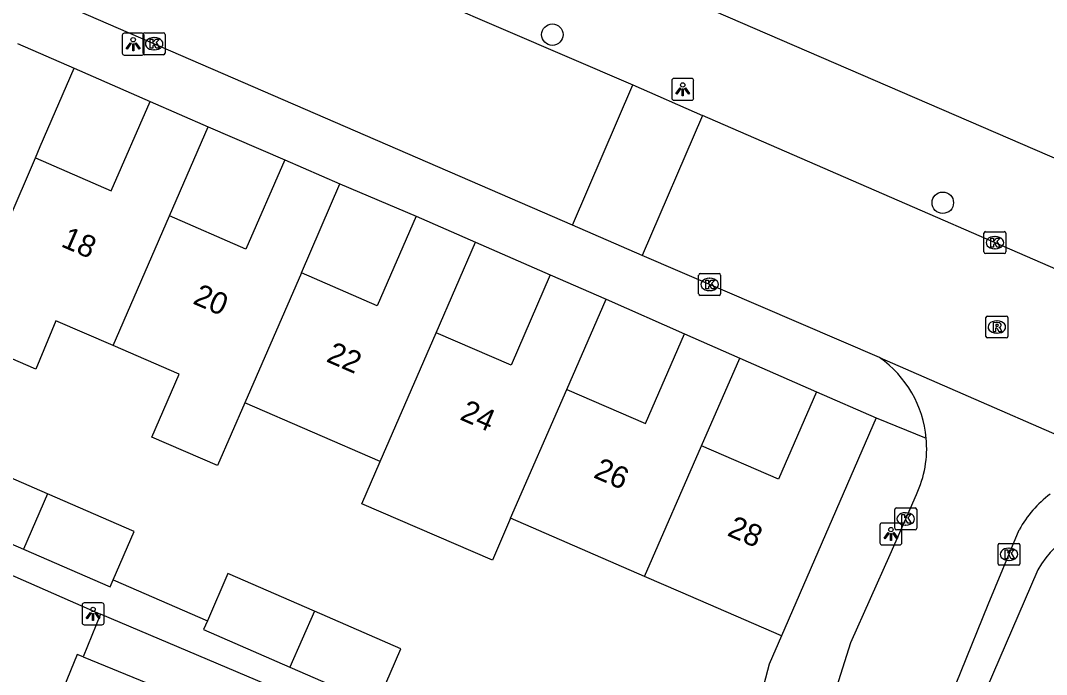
# Model space of a CAD drawing. Extents: x 162812 to 163818, y 381639 to 382470.
# Drawn here: x 163306.17 to 163352.9, y 381949.74 to 381979.54 of the extents above; entities that cross this region are included whole.
import ezdxf

# ---------------------------------------------------------------- set-up
doc = ezdxf.new("R2010")
doc.units = 0
for name, color, linetype in [('IMGEO_Boom', 7, 'Continuous'), ('IMGEO_Kolk', 7, 'Continuous'), ('IMGEO_Lichtpunt', 7, 'Continuous'), ('IMGEO_Pand', 7, 'Continuous'), ('IMGEO_Pand_nummerreeks', 7, 'Continuous'), ('IMGEO_Rijbaan_lokaal_open', 7, 'Continuous'), ('IMGEO_Rioolput', 7, 'Continuous'), ('IMGEO_Voetpad_open', 7, 'Continuous')]:
    doc.layers.add(name, color=color, linetype=linetype)

msp = doc.modelspace()

# ---------------------------------------------------------------- linework, layer by layer
at = {"layer": 'IMGEO_Boom'}
for centre in [(163330.392, 381978.896), (163348.173, 381971.236)]:
    msp.add_circle(centre, 0.489, dxfattribs=at)
at = {"layer": 'IMGEO_Kolk'}
for p, q in [((163311.756, 381978.057), (163311.756, 381978.909)), ((163311.831, 381978.983), (163312.683, 381978.983)), ((163312.244, 381978.763), (163312.269, 381978.763)), ((163312.757, 381978.909), (163312.757, 381978.057)), ((163312.683, 381977.983), (163311.831, 381977.983)), ((163312.267, 381978.203), (163312.242, 381978.203)), ((163350.121, 381969.919), (163350.973, 381969.919)), ((163350.046, 381968.993), (163350.046, 381969.845)), ((163350.534, 381969.699), (163350.559, 381969.699)), ((163351.047, 381969.845), (163351.047, 381968.993)), ((163350.557, 381969.139), (163350.532, 381969.139)), ((163350.973, 381968.919), (163350.121, 381968.919)), ((163337.13, 381968.015), (163337.982, 381968.015)), ((163337.055, 381967.089), (163337.055, 381967.941)), ((163337.543, 381967.795), (163337.568, 381967.795)), ((163338.056, 381967.941), (163338.056, 381967.089)), ((163337.566, 381967.235), (163337.541, 381967.235)), ((163337.982, 381967.015), (163337.13, 381967.015)), ((163345.986, 381956.405), (163345.986, 381957.257)), ((163346.061, 381957.331), (163346.913, 381957.331)), ((163346.987, 381957.257), (163346.987, 381956.405)), ((163346.474, 381957.111), (163346.499, 381957.111)), ((163346.913, 381956.331), (163346.061, 381956.331)), ((163346.497, 381956.551), (163346.472, 381956.551)), ((163350.688, 381954.792), (163350.688, 381955.644)), ((163350.763, 381955.718), (163351.615, 381955.718)), ((163351.176, 381955.498), (163351.201, 381955.498)), ((163351.689, 381955.644), (163351.689, 381954.792)), ((163351.199, 381954.938), (163351.174, 381954.938)), ((163351.615, 381954.718), (163350.763, 381954.718))]:
    msp.add_line(p, q, dxfattribs=at)
for points in [[(163311.756, 381978.057), (163311.756, 381978.909)], [(163311.831, 381978.983), (163312.683, 381978.983)], [(163312.757, 381978.909), (163312.757, 381978.057)], [(163312.077, 381978.683), (163312.2, 381978.683), (163312.2, 381978.532), (163312.33, 381978.683), (163312.494, 381978.683), (163312.348, 381978.532), (163312.501, 381978.283), (163312.349, 381978.283), (163312.264, 381978.447), (163312.2, 381978.38), (163312.2, 381978.283), (163312.077, 381978.283), (163312.077, 381978.683)], [(163312.683, 381977.983), (163311.831, 381977.983)], [(163350.121, 381969.919), (163350.973, 381969.919)], [(163350.046, 381968.993), (163350.046, 381969.845)], [(163350.367, 381969.619), (163350.49, 381969.619), (163350.49, 381969.468), (163350.62, 381969.619), (163350.784, 381969.619), (163350.638, 381969.468), (163350.791, 381969.219), (163350.639, 381969.219), (163350.554, 381969.383), (163350.49, 381969.316), (163350.49, 381969.219), (163350.367, 381969.219), (163350.367, 381969.619)], [(163351.047, 381969.845), (163351.047, 381968.993)], [(163350.973, 381968.919), (163350.121, 381968.919)], [(163337.13, 381968.015), (163337.982, 381968.015)], [(163337.055, 381967.089), (163337.055, 381967.941)], [(163337.376, 381967.715), (163337.499, 381967.715), (163337.499, 381967.564), (163337.629, 381967.715), (163337.793, 381967.715), (163337.647, 381967.564), (163337.8, 381967.315), (163337.648, 381967.315), (163337.563, 381967.479), (163337.499, 381967.412), (163337.499, 381967.315), (163337.376, 381967.315), (163337.376, 381967.715)], [(163338.056, 381967.941), (163338.056, 381967.089)], [(163337.982, 381967.015), (163337.13, 381967.015)], [(163345.986, 381956.405), (163345.986, 381957.257)], [(163346.061, 381957.331), (163346.913, 381957.331)], [(163346.987, 381957.257), (163346.987, 381956.405)], [(163346.307, 381957.031), (163346.43, 381957.031), (163346.43, 381956.88), (163346.56, 381957.031), (163346.724, 381957.031), (163346.578, 381956.88), (163346.731, 381956.631), (163346.579, 381956.631), (163346.494, 381956.795), (163346.43, 381956.728), (163346.43, 381956.631), (163346.307, 381956.631), (163346.307, 381957.031)], [(163346.913, 381956.331), (163346.061, 381956.331)], [(163350.688, 381954.792), (163350.688, 381955.644)], [(163350.763, 381955.718), (163351.615, 381955.718)], [(163351.009, 381955.418), (163351.132, 381955.418), (163351.132, 381955.267), (163351.262, 381955.418), (163351.426, 381955.418), (163351.28, 381955.267), (163351.433, 381955.018), (163351.281, 381955.018), (163351.196, 381955.182), (163351.132, 381955.115), (163351.132, 381955.018), (163351.009, 381955.018), (163351.009, 381955.418)], [(163351.689, 381955.644), (163351.689, 381954.792)], [(163351.615, 381954.718), (163350.763, 381954.718)]]:
    msp.add_lwpolyline(points, dxfattribs=at)
for centre, start, end in [((163311.833, 381978.907), 91.552, 178.448), ((163311.833, 381978.907), 91.552, 178.448), ((163312.681, 381978.907), 1.552, 88.448), ((163312.681, 381978.907), 1.552, 88.448), ((163311.833, 381978.059), 181.552, 268.448), ((163311.833, 381978.059), 181.552, 268.448), ((163312.681, 381978.059), 271.552, 358.448), ((163312.681, 381978.059), 271.552, 358.448), ((163350.123, 381969.843), 91.552, 178.448), ((163350.123, 381969.843), 91.552, 178.448), ((163350.971, 381969.843), 1.552, 88.448), ((163350.971, 381969.843), 1.552, 88.448), ((163350.123, 381968.995), 181.552, 268.448), ((163350.123, 381968.995), 181.552, 268.448), ((163350.971, 381968.995), 271.552, 358.448), ((163350.971, 381968.995), 271.552, 358.448), ((163337.132, 381967.939), 91.552, 178.448), ((163337.132, 381967.939), 91.552, 178.448), ((163337.98, 381967.939), 1.552, 88.448), ((163337.98, 381967.939), 1.552, 88.448), ((163337.132, 381967.091), 181.552, 268.448), ((163337.132, 381967.091), 181.552, 268.448), ((163337.98, 381967.091), 271.552, 358.448), ((163337.98, 381967.091), 271.552, 358.448), ((163346.063, 381957.255), 91.552, 178.448), ((163346.063, 381957.255), 91.552, 178.448), ((163346.911, 381957.255), 1.552, 88.448), ((163346.911, 381957.255), 1.552, 88.448), ((163346.063, 381956.407), 181.552, 268.448), ((163346.063, 381956.407), 181.552, 268.448), ((163346.911, 381956.407), 271.552, 358.448), ((163346.911, 381956.407), 271.552, 358.448), ((163350.765, 381955.642), 91.552, 178.448), ((163350.765, 381955.642), 91.552, 178.448), ((163351.613, 381955.642), 1.552, 88.448), ((163351.613, 381955.642), 1.552, 88.448), ((163350.765, 381954.794), 181.552, 268.448), ((163350.765, 381954.794), 181.552, 268.448), ((163351.613, 381954.794), 271.552, 358.448), ((163351.613, 381954.794), 271.552, 358.448)]:
    msp.add_arc(centre, 0.0765, start, end, dxfattribs=at)
for centre, major_axis, ratio, start_param, end_param in [((163312.243, 381978.483), (-0.387, 0.002), 0.722429, 4.712389, 7.853982), ((163312.268, 381978.483), (-0.39, 0.002), 0.717154, 1.570796, 4.712389), ((163350.533, 381969.419), (-0.387, 0.002), 0.722429, 4.712389, 7.853982), ((163350.558, 381969.419), (-0.39, 0.002), 0.717154, 1.570796, 4.712389), ((163337.542, 381967.515), (-0.387, 0.002), 0.722429, 4.712389, 7.853982), ((163337.567, 381967.515), (-0.39, 0.002), 0.717154, 1.570796, 4.712389), ((163346.473, 381956.831), (-0.387, 0.002), 0.722429, 4.712389, 7.853982), ((163346.498, 381956.831), (-0.39, 0.002), 0.717154, 1.570796, 4.712389), ((163351.175, 381955.218), (-0.387, 0.002), 0.722429, 4.712389, 7.853982), ((163351.2, 381955.218), (-0.39, 0.002), 0.717154, 1.570796, 4.712389)]:
    msp.add_ellipse(centre, major_axis=major_axis, ratio=ratio, start_param=start_param, end_param=end_param, dxfattribs=at)
at = {"layer": 'IMGEO_Lichtpunt'}
for p, q in [((163310.802, 381978.865), (163310.802, 381978.058)), ((163310.802, 381978.865), (163310.802, 381978.058)), ((163311.704, 381978.96), (163310.896, 381978.96)), ((163311.704, 381978.96), (163310.896, 381978.96)), ((163311.798, 381978.058), (163311.798, 381978.865)), ((163311.798, 381978.058), (163311.798, 381978.865)), ((163310.896, 381977.964), (163311.704, 381977.964)), ((163310.896, 381977.964), (163311.704, 381977.964)), ((163336.733, 381976.903), (163335.925, 381976.903)), ((163336.733, 381976.903), (163335.925, 381976.903)), ((163335.831, 381976.808), (163335.831, 381976.001)), ((163335.831, 381976.808), (163335.831, 381976.001)), ((163336.827, 381976.001), (163336.827, 381976.808)), ((163336.827, 381976.001), (163336.827, 381976.808)), ((163335.925, 381975.907), (163336.733, 381975.907)), ((163335.925, 381975.907), (163336.733, 381975.907)), ((163345.312, 381956.548), (163345.312, 381955.741)), ((163345.312, 381956.548), (163345.312, 381955.741)), ((163346.214, 381956.643), (163345.406, 381956.643)), ((163346.214, 381956.643), (163345.406, 381956.643)), ((163346.308, 381955.741), (163346.308, 381956.548)), ((163346.308, 381955.741), (163346.308, 381956.548)), ((163345.406, 381955.647), (163346.214, 381955.647)), ((163345.406, 381955.647), (163346.214, 381955.647)), ((163308.977, 381952.91), (163308.977, 381952.103)), ((163308.977, 381952.91), (163308.977, 381952.103)), ((163309.879, 381953.005), (163309.071, 381953.005)), ((163309.879, 381953.005), (163309.071, 381953.005)), ((163309.973, 381952.103), (163309.973, 381952.91)), ((163309.973, 381952.103), (163309.973, 381952.91)), ((163309.071, 381952.009), (163309.879, 381952.009)), ((163309.071, 381952.009), (163309.879, 381952.009))]:
    msp.add_line(p, q, dxfattribs=at)
for points in [[(163311.176, 381978.529), (163311.215, 381978.501), (163311.027, 381978.239), (163310.989, 381978.266), (163311.176, 381978.529)], [(163311.278, 381978.481), (163311.325, 381978.481), (163311.325, 381978.159), (163311.278, 381978.159), (163311.278, 381978.481)], [(163311.388, 381978.501), (163311.426, 381978.528), (163311.613, 381978.266), (163311.574, 381978.238), (163311.388, 381978.501)], [(163336.205, 381976.472), (163336.244, 381976.444), (163336.056, 381976.182), (163336.018, 381976.209), (163336.205, 381976.472)], [(163336.307, 381976.424), (163336.354, 381976.424), (163336.354, 381976.102), (163336.307, 381976.102), (163336.307, 381976.424)], [(163336.417, 381976.444), (163336.455, 381976.471), (163336.642, 381976.209), (163336.603, 381976.181), (163336.417, 381976.444)], [(163345.686, 381956.212), (163345.725, 381956.184), (163345.537, 381955.922), (163345.499, 381955.949), (163345.686, 381956.212)], [(163345.788, 381956.164), (163345.835, 381956.164), (163345.835, 381955.842), (163345.788, 381955.842), (163345.788, 381956.164)], [(163345.898, 381956.184), (163345.936, 381956.211), (163346.123, 381955.949), (163346.084, 381955.921), (163345.898, 381956.184)], [(163309.351, 381952.574), (163309.39, 381952.546), (163309.202, 381952.284), (163309.164, 381952.311), (163309.351, 381952.574)], [(163309.453, 381952.526), (163309.5, 381952.526), (163309.5, 381952.204), (163309.453, 381952.204), (163309.453, 381952.526)], [(163309.563, 381952.546), (163309.601, 381952.573), (163309.788, 381952.311), (163309.749, 381952.283), (163309.563, 381952.546)]]:
    msp.add_lwpolyline(points, dxfattribs=at)
for centre in [(163311.301, 381978.663), (163336.33, 381976.606), (163345.811, 381956.346), (163309.476, 381952.708)]:
    msp.add_circle(centre, 0.0994, dxfattribs=at)
for centre, start, end in [((163310.896, 381978.865), 90, 180), ((163310.896, 381978.865), 90, 180), ((163311.704, 381978.865), 0, 90), ((163311.704, 381978.865), 0, 90), ((163310.896, 381978.058), 180, 270), ((163310.896, 381978.058), 180, 270), ((163311.704, 381978.058), 270, 0), ((163311.704, 381978.058), 270, 360), ((163335.925, 381976.808), 90, 180), ((163335.925, 381976.808), 90, 180), ((163336.733, 381976.808), 0, 90), ((163336.733, 381976.808), 0, 90), ((163335.925, 381976.001), 180, 270), ((163335.925, 381976.001), 180, 270), ((163336.733, 381976.001), 270, 0), ((163336.733, 381976.001), 270, 360), ((163345.406, 381956.548), 90, 180), ((163345.406, 381956.548), 90, 180), ((163346.214, 381956.548), 0, 90), ((163346.214, 381956.548), 0, 90), ((163345.406, 381955.741), 180, 270), ((163345.406, 381955.741), 180, 270), ((163346.214, 381955.741), 270, 0), ((163346.214, 381955.741), 270, 360), ((163309.071, 381952.91), 90, 180), ((163309.071, 381952.91), 90, 180), ((163309.879, 381952.91), 0, 90), ((163309.879, 381952.91), 0, 90), ((163309.071, 381952.103), 180, 270), ((163309.071, 381952.103), 180, 270), ((163309.879, 381952.103), 270, 0), ((163309.879, 381952.103), 270, 360)]:
    msp.add_arc(centre, 0.0946, start, end, dxfattribs=at)
at = {"layer": 'IMGEO_Pand'}
for points in [[(163306.036, 381978.49), (163308.618, 381977.367)], [(163306.847, 381973.288), (163307.065, 381973.796), (163308.618, 381977.367)], [(163306.847, 381973.288), (163310.306, 381971.785), (163312.073, 381975.849)], [(163312.073, 381975.849), (163314.721, 381974.698)], [(163312.956, 381970.637), (163314.721, 381974.698)], [(163304.301, 381967.373), (163306.847, 381973.288)], [(163318.209, 381973.193), (163316.439, 381969.122), (163312.956, 381970.637)], [(163318.209, 381973.193), (163320.72, 381972.101)], [(163318.96, 381968.044), (163320.72, 381972.101)], [(163310.39, 381964.726), (163312.956, 381970.637)], [(163324.189, 381970.625), (163322.415, 381966.543), (163318.96, 381968.044)], [(163324.189, 381970.625), (163326.897, 381969.448)], [(163325.099, 381965.314), (163326.897, 381969.448)], [(163318.96, 381968.044), (163316.388, 381962.119)], [(163330.299, 381967.946), (163328.51, 381963.831), (163325.099, 381965.314)], [(163330.299, 381967.946), (163332.835, 381966.844)], [(163310.39, 381964.726), (163307.779, 381965.861), (163306.866, 381963.652), (163303.388, 381965.164), (163304.301, 381967.373)], [(163331.045, 381962.73), (163332.835, 381966.844)], [(163322.55, 381959.44), (163325.099, 381965.314)], [(163331.045, 381962.73), (163334.629, 381961.172), (163336.405, 381965.257)], [(163336.405, 381965.257), (163338.923, 381964.162)], [(163316.388, 381962.119), (163315.144, 381959.258), (163312.152, 381960.558), (163313.396, 381963.42), (163310.39, 381964.726)], [(163337.185, 381960.16), (163338.923, 381964.162)], [(163328.491, 381956.858), (163331.045, 381962.73)], [(163342.419, 381962.629), (163340.685, 381958.639), (163337.185, 381960.16)], [(163342.419, 381962.629), (163345.145, 381961.444)], [(163322.55, 381959.44), (163316.388, 381962.119)], [(163345.145, 381961.444), (163340.821, 381951.498)], [(163334.594, 381954.205), (163337.185, 381960.16)], [(163307.4, 381957.977), (163303.447, 381959.695), (163302.488, 381957.49)], [(163328.491, 381956.858), (163327.66, 381954.948), (163321.719, 381957.526), (163322.55, 381959.44)], [(163307.4, 381957.977), (163306.305, 381955.457)], [(163310.395, 381954.055), (163311.353, 381956.259), (163307.4, 381957.977)], [(163302.488, 381957.49), (163302.352, 381957.176), (163306.305, 381955.457)], [(163334.594, 381954.205), (163328.491, 381956.858)], [(163306.305, 381955.457), (163310.258, 381953.739), (163310.395, 381954.055)], [(163319.554, 381952.63), (163315.617, 381954.341), (163314.683, 381952.192)], [(163340.821, 381951.498), (163336.236, 381953.491), (163334.594, 381954.205)], [(163319.554, 381952.63), (163318.443, 381950.075)], [(163322.558, 381948.77), (163323.491, 381950.918), (163319.554, 381952.63)], [(163314.683, 381952.192), (163314.506, 381951.786), (163318.443, 381950.075)], [(163309.024, 381950.542), (163308.747, 381950.655), (163307.195, 381946.864)], [(163309.024, 381950.542), (163314.886, 381948.141), (163313.334, 381944.351)], [(163318.443, 381950.075), (163322.381, 381948.363), (163322.558, 381948.77)]]:
    msp.add_lwpolyline(points, dxfattribs=at)
at = {"layer": 'IMGEO_Rijbaan_lokaal_open'}
for points in [[(163331.307, 381970.219), (163302.214, 381982.84), (163298.707, 381984.363), (163297.541, 381984.881)], [(163319.351, 381982.939), (163334.063, 381976.602)], [(163331.307, 381970.219), (163334.063, 381976.602)], [(163334.063, 381976.602), (163337.225, 381975.21)], [(163337.225, 381975.21), (163334.486, 381968.838)], [(163360.196, 381965.225), (163337.225, 381975.21)], [(163334.486, 381968.838), (163331.307, 381970.219)], [(163345.294, 381964.18), (163334.486, 381968.838)], [(163345.294, 381964.18), (163357.753, 381958.749)], [(163326.344, 381885.984), (163328.227, 381892.894), (163341.305, 381941.763), (163342.269, 381945.397), (163342.879, 381947.698), (163343.979, 381951.2), (163345.777, 381955.212), (163346.974, 381957.941)], [(163336.429, 381904.454), (163347.786, 381946.853), (163350.24, 381952.934), (163351.653, 381956.334)], [(163302.999, 381955.478), (163309.811, 381952.487)], [(163309.811, 381952.487), (163309.024, 381950.542)]]:
    msp.add_lwpolyline(points, dxfattribs=at)
for centre, radius, start, end in [((163342.403, 381960.055), 5.037, 5.0999, 54.9722), ((163342.396, 381960.058), 5.044, 335.1853, 5.0642), ((163356.137, 381953.875), 5.114, 126.8922, 151.2603)]:
    msp.add_arc(centre, radius, start, end, dxfattribs=at)
at = {"layer": 'IMGEO_Rioolput'}
for p, q in [((163350.134, 381965.149), (163350.134, 381966.001)), ((163350.209, 381966.075), (163351.061, 381966.075)), ((163350.622, 381965.855), (163350.647, 381965.855)), ((163351.135, 381966.001), (163351.135, 381965.149)), ((163350.645, 381965.295), (163350.62, 381965.295)), ((163351.061, 381965.075), (163350.209, 381965.075))]:
    msp.add_line(p, q, dxfattribs=at)
for points in [[(163350.134, 381965.149), (163350.134, 381966.001)], [(163350.209, 381966.075), (163351.061, 381966.075)], [(163350.723, 381965.773), (163350.471, 381965.775), (163350.471, 381965.375)], [(163350.649, 381965.694), (163350.595, 381965.694), (163350.595, 381965.613)], [(163351.135, 381966.001), (163351.135, 381965.149)], [(163350.471, 381965.375), (163350.595, 381965.375), (163350.595, 381965.537), (163350.606, 381965.537)], [(163350.595, 381965.613), (163350.647, 381965.613)], [(163350.653, 381965.508), (163350.724, 381965.375), (163350.864, 381965.375), (163350.799, 381965.501)], [(163351.061, 381965.075), (163350.209, 381965.075)]]:
    msp.add_lwpolyline(points, dxfattribs=at)
for centre, radius, start, end in [((163350.211, 381965.999), 0.0765, 91.552, 178.448), ((163350.211, 381965.999), 0.0765, 91.552, 178.448), ((163350.655, 381965.598), 0.0964, 77.0061, 93.1865), ((163350.669, 381965.655), 0.0378, 276.6634, 79.6772), ((163350.722, 381965.663), 0.109, 350.3612, 89.416), ((163351.059, 381965.999), 0.0765, 1.552, 88.448), ((163351.059, 381965.999), 0.0765, 1.552, 88.448), ((163350.605, 381965.484), 0.0533, 26.0293, 88.6989), ((163350.631, 381965.802), 0.19, 274.7715, 282.9687), ((163350.72, 381965.663), 0.112, 277.5842, 350.9817), ((163350.704, 381965.448), 0.108, 29.5134, 73.7905), ((163350.211, 381965.151), 0.0765, 181.552, 268.448), ((163350.211, 381965.151), 0.0765, 181.552, 268.448), ((163351.059, 381965.151), 0.0765, 271.552, 358.448), ((163351.059, 381965.151), 0.0765, 271.552, 358.448)]:
    msp.add_arc(centre, radius, start, end, dxfattribs=at)
for centre, major_axis, ratio, start_param, end_param in [((163350.621, 381965.575), (-0.387, 0.002), 0.722429, 4.712389, 7.853982), ((163350.646, 381965.575), (-0.39, 0.002), 0.717154, 1.570796, 4.712389)]:
    msp.add_ellipse(centre, major_axis=major_axis, ratio=ratio, start_param=start_param, end_param=end_param, dxfattribs=at)
at = {"layer": 'IMGEO_Voetpad_open'}
for points in [[(163322.499, 381986.595), (163361.532, 381969.699), (163362.423, 381969.31)], [(163308.618, 381977.367), (163312.073, 381975.849)], [(163314.721, 381974.698), (163318.209, 381973.193)], [(163320.72, 381972.101), (163324.189, 381970.625)], [(163326.897, 381969.448), (163330.299, 381967.946)], [(163332.835, 381966.844), (163336.405, 381965.257)], [(163338.923, 381964.162), (163342.419, 381962.629)], [(163345.145, 381961.444), (163347.42, 381960.503)], [(163352.498, 381954.506), (163350.15, 381949.06), (163349.232, 381946.25), (163337.135, 381901.001)], [(163310.395, 381954.055), (163314.683, 381952.192)], [(163337.762, 381940.645), (163309.811, 381952.487)], [(163340.821, 381951.498), (163340.262, 381950.209), (163338.117, 381942.001)]]:
    msp.add_lwpolyline(points, dxfattribs=at)
msp.add_arc((163355.818, 381952.712), 3.774, 73.743, 151.6138, dxfattribs=at)

# ---------------------------------------------------------------- texts
at = {"layer": 'IMGEO_Pand_nummerreeks'}
for s, rotation, p in [('18', 336.5335, (163307.969, 381969.264)), ('20', 336.5316, (163313.97, 381966.659)), ('22', 336.5335, (163320.049, 381964.02)), ('24', 336.5316, (163326.135, 381961.377)), ('26', 336.5316, (163332.219, 381958.736)), ('28', 336.5335, (163338.308, 381956.094))]:
    msp.add_text(s, height=1, rotation=rotation, dxfattribs=at).set_placement(p)

doc.saveas('drawing.dxf')
